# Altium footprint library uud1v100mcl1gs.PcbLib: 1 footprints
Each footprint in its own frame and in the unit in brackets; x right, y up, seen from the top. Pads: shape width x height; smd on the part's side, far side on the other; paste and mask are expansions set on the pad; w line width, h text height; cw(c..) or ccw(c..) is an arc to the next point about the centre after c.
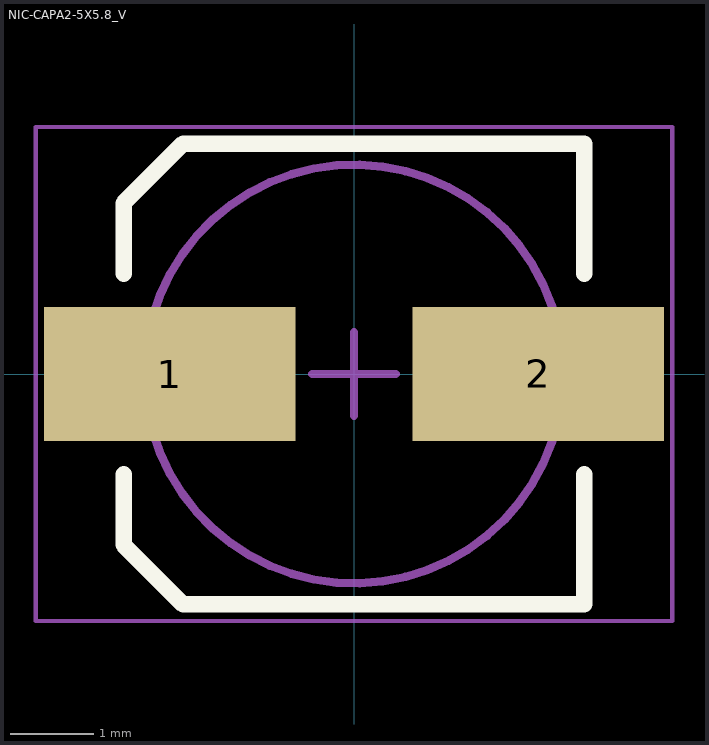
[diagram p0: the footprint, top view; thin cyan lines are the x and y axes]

## NIC-CAPA2-5X5.8_V [mm] "Aluminum Electrolytic Capacitor, Diameter 5mm, Height 6.1mm, Pitch 4.4mm"
height 6.1
pads (2):
  rect 3x1.6 smd: 1(-2.2,0) 2(2.2,0)
Top Overlay:
  lines w0.2: -2.75,-1.2 -2.75,-2.04 -2.04,-2.75 2.75,-2.75 2.75,-1.2 ; -2.75,1.2 -2.75,2.04 -2.04,2.75 2.75,2.75 2.75,1.2
Mechanical 13:
  circle w0.1: c0,0 r2.5
Mechanical 15:
  lines w0.05: -3.8,-2.95 -3.8,2.95 3.8,2.95 3.8,-2.95 -3.8,-2.95
  lines w0.1: -0.5,0 0.5,0 ; 0,-0.5 0,0.5
3D body: height 6.1, standoff 0, extent -2.495,-2.48 2.495,2.5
